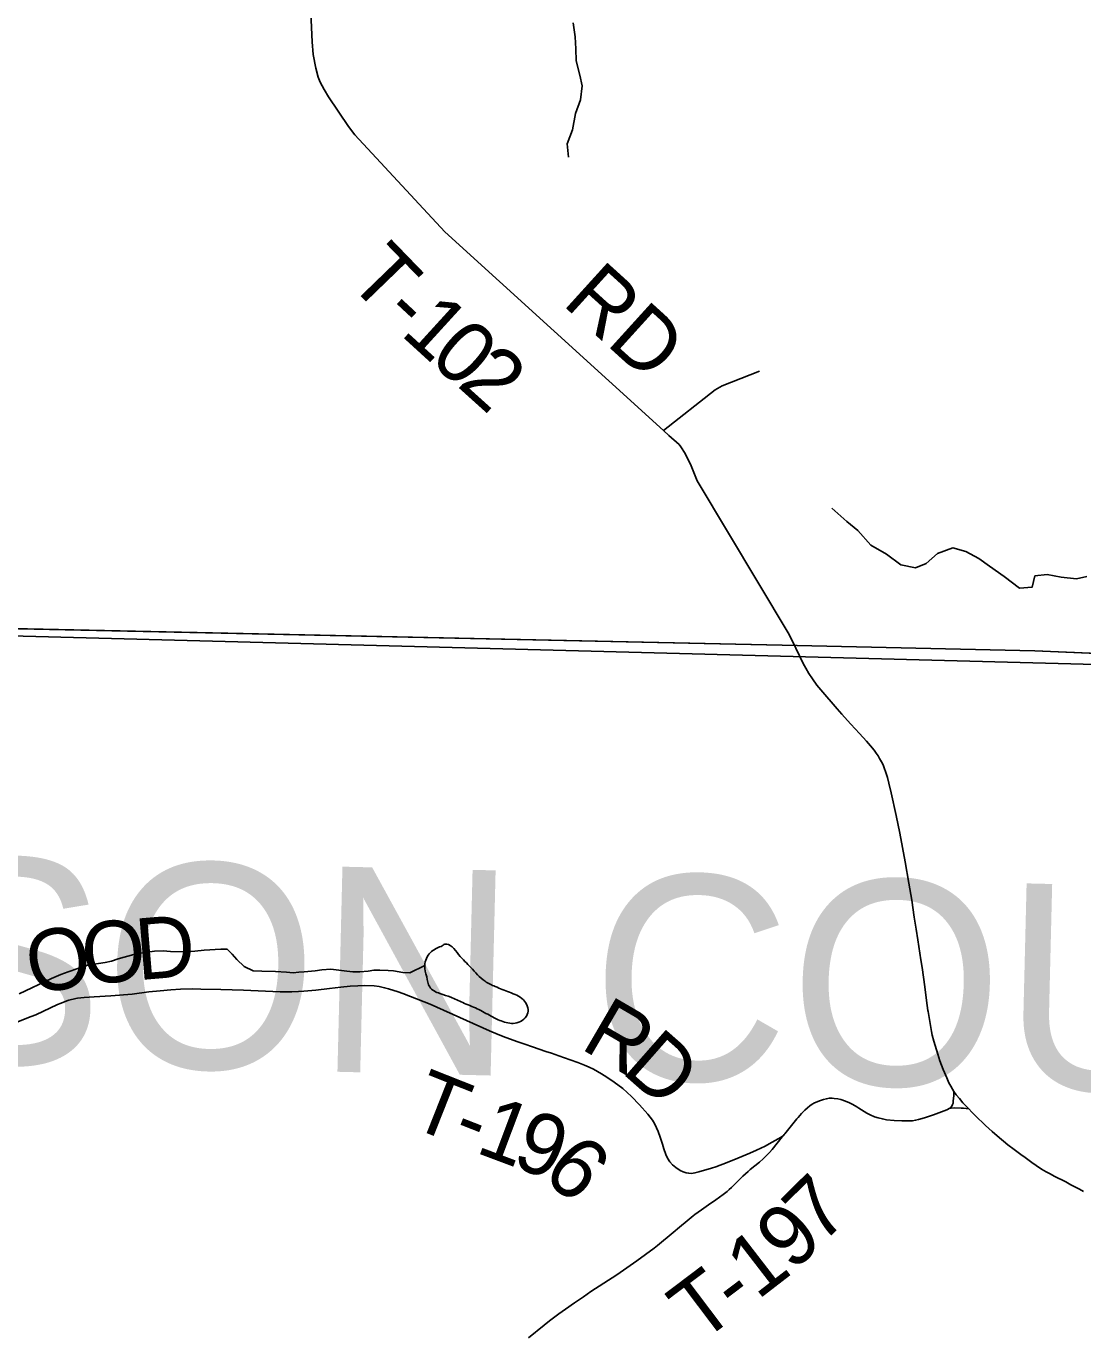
# Model space of a CAD drawing. Extents: x -1.2 to 34, y -8.5 to 22.
# Drawn here: x 3.478 to 4.454, y 17.02 to 18.225 of the extents above; entities that cross this region are included whole.
import ezdxf

# ---------------------------------------------------------------- set-up
doc = ezdxf.new("R2010")
doc.units = 0
for name, color, linetype in [('DV_X_County_Line', 7, 'Continuous'), ('GM_X_County_Road', 7, 'Continuous'), ('GM_X_County_Text', 7, 'Continuous'), ('GM_X_Minor_River', 7, 'Continuous'), ('GM_X_Township_Road', 7, 'Continuous'), ('GM_X_Township_Road_Text', 7, 'Continuous'), ('GM_X_Unincorporated_Text', 7, 'Continuous'), ('SH_Cut_Line', 7, 'Continuous')]:
    doc.layers.add(name, color=color, linetype=linetype)

msp = doc.modelspace()

# ---------------------------------------------------------------- linework, layer by layer
at = {"layer": 'DV_X_County_Line'}
msp.add_lwpolyline([(2.4258, 17.6899), (5.4446, 17.6102), (5.4511, 17.7337), (6.5684, 17.7149)], dxfattribs=at)
at = {"layer": 'GM_X_County_Road'}
msp.add_lwpolyline([(4.1824, 17.6639), (4.1886, 17.6513), (4.1955, 17.6371), (4.1977, 17.6329), (4.2007, 17.628), (4.2041, 17.6228), (4.2081, 17.6172), (4.2117, 17.6127), (4.2267, 17.5951), (4.231, 17.5902), (4.2362, 17.5846), (4.2395, 17.581), (4.2475, 17.5725), (4.254, 17.5654), (4.2576, 17.5611), (4.2608, 17.5571), (4.2629, 17.5544), (4.2646, 17.5518), (4.266, 17.5494), (4.2678, 17.5463), (4.2691, 17.5435), (4.2702, 17.5408), (4.2716, 17.5365), (4.2731, 17.5318), (4.2745, 17.5266), (4.2766, 17.5177), (4.2811, 17.4968), (4.2846, 17.4804), (4.2896, 17.4541), (4.293, 17.4344), (4.2957, 17.4186), (4.298, 17.403), (4.2998, 17.392), (4.3012, 17.3821), (4.3022, 17.376), (4.3041, 17.3637), (4.3052, 17.3565), (4.3065, 17.3476), (4.3077, 17.3385), (4.3094, 17.3261), (4.3106, 17.3168), (4.3107, 17.3158), (4.3139, 17.2974), (4.3145, 17.294), (4.3159, 17.2886), (4.3196, 17.2764), (4.3217, 17.2703), (4.3247, 17.2624), (4.3279, 17.2547), (4.33, 17.25), (4.3316, 17.2469), (4.3333, 17.2442), (4.3346, 17.2421), (4.3368, 17.2389), (4.3396, 17.2354), (4.3429, 17.2315), (4.3482, 17.226), (4.3512, 17.2229), (4.3541, 17.22), (4.3637, 17.2107), (4.3699, 17.205), (4.3745, 17.2011), (4.3845, 17.1929), (4.3903, 17.1884), (4.3963, 17.1839), (4.4003, 17.181), (4.4065, 17.1764), (4.4104, 17.1736), (4.4153, 17.1704), (4.4197, 17.1678), (4.4233, 17.1659), (4.4271, 17.1639), (4.4378, 17.1585), (4.4425, 17.156), (4.4469, 17.1537), (4.4505, 17.1517), (4.4541, 17.1496)], dxfattribs=at)
at = {"layer": 'GM_X_Minor_River'}
for points in [[(3.9831, 18.2284), (3.9847, 18.2155), (3.9856, 18.2045), (3.9857, 18.1935), (3.9892, 18.1803), (3.9912, 18.1704), (3.9898, 18.1575), (3.9853, 18.1449), (3.9824, 18.1297)], [(3.9824, 18.1297), (3.9776, 18.1167), (3.9788, 18.1046)], [(4.4572, 17.7173), (4.4477, 17.7153), (4.4337, 17.7167), (4.4207, 17.7192), (4.4093, 17.718), (4.4068, 17.7074), (4.395, 17.7065), (4.3809, 17.7174), (4.3675, 17.7268), (4.3576, 17.7339), (4.3457, 17.7406), (4.3335, 17.7439), (4.3195, 17.7385), (4.309, 17.7293), (4.2991, 17.7254), (4.2854, 17.7283), (4.2724, 17.7381), (4.2579, 17.7463), (4.246, 17.7599), (4.2357, 17.7681), (4.2219, 17.7805)], [(3.4713, 17.3321), (3.5014, 17.3463), (3.51, 17.3499), (3.5168, 17.3526), (3.5345, 17.3586), (3.5508, 17.3611), (3.5568, 17.3624), (3.5628, 17.3644), (3.5772, 17.3684), (3.5836, 17.3696), (3.5964, 17.3714), (3.6044, 17.3719), (3.6112, 17.3712), (3.6237, 17.371), (3.6335, 17.3716), (3.6422, 17.3724), (3.6577, 17.3734)], [(3.6577, 17.3734), (3.6634, 17.3735), (3.668, 17.3687), (3.6723, 17.3638), (3.6792, 17.3574), (3.6876, 17.3533), (3.6955, 17.3531), (3.708, 17.3529), (3.7183, 17.3523), (3.7243, 17.3516), (3.7296, 17.3521), (3.7345, 17.3525), (3.7447, 17.3535), (3.7508, 17.3543), (3.7591, 17.3548), (3.7739, 17.3531), (3.7796, 17.3525), (3.786, 17.3526), (3.7936, 17.3531), (3.7989, 17.3539), (3.8046, 17.354), (3.8121, 17.3537), (3.8171, 17.3534), (3.8258, 17.352), (3.8322, 17.3517), (3.8459, 17.3583)]]:
    msp.add_lwpolyline(points, dxfattribs=at)
for points in [[(3.861, 17.376), (3.8512, 17.3704), (3.8459, 17.3583), (3.8478, 17.348)], [(3.8478, 17.348), (3.8505, 17.3385), (3.86, 17.3324), (3.8699, 17.329), (3.881, 17.3241), (3.8943, 17.3184), (3.9073, 17.3115), (3.918, 17.3066), (3.931, 17.3054), (3.9412, 17.3146), (3.937, 17.3267), (3.9241, 17.3336), (3.9111, 17.3389), (3.9016, 17.3438), (3.8886, 17.3564), (3.8772, 17.3685), (3.8646, 17.378), (3.861, 17.376)]]:
    msp.add_spline(points, degree=3, dxfattribs=at)
at = {"layer": 'GM_X_Township_Road'}
for points in [[(4.1824, 17.6639), (4.0975, 17.8056), (4.0919, 17.8196), (4.0864, 17.8309), (4.0824, 17.8372), (4.0809, 17.8391), (4.0712, 17.8477), (4.0663, 17.8522), (3.8645, 18.0357), (3.7814, 18.1252), (3.7754, 18.1328), (3.7572, 18.1601), (3.753, 18.1668), (3.7493, 18.1737), (3.7476, 18.1782), (3.7453, 18.1865), (3.7428, 18.1991), (3.7419, 18.2108), (3.7375, 18.3122)], [(4.0663, 17.8522), (4.1142, 17.8896), (4.1207, 17.8933), (4.1552, 17.907)], [(3.4678, 17.3054), (3.4826, 17.3111), (3.4867, 17.3128), (3.5069, 17.3222), (3.5102, 17.3237), (3.5154, 17.3257), (3.5173, 17.3263), (3.5238, 17.328), (3.5253, 17.3282), (3.5316, 17.3287), (3.5407, 17.3293), (3.556, 17.3302), (3.5758, 17.332), (3.5913, 17.3339), (3.6015, 17.335), (3.6116, 17.336), (3.6204, 17.3365), (3.6314, 17.3368), (3.6391, 17.3366), (3.6576, 17.3363), (3.6787, 17.3357), (3.7123, 17.334), (3.717, 17.3339), (3.7232, 17.3339), (3.7295, 17.3342), (3.7343, 17.3346), (3.7454, 17.3357), (3.7579, 17.3371), (3.7684, 17.3382), (3.7771, 17.3391), (3.7841, 17.3397), (3.7901, 17.3399), (3.7991, 17.3395), (3.8038, 17.3389), (3.8088, 17.3378), (3.8126, 17.3368), (3.8215, 17.3339), (3.8257, 17.3324), (3.8455, 17.3248), (3.8508, 17.3226), (3.8844, 17.3076), (3.9058, 17.298), (3.9137, 17.2946), (3.9208, 17.2919), (3.932, 17.2879), (3.9383, 17.2857), (3.9454, 17.2832), (3.9515, 17.2811), (3.9578, 17.279), (3.9629, 17.2773), (3.9697, 17.2749), (3.975, 17.2731), (3.9803, 17.2712), (3.9873, 17.2687), (3.9936, 17.2663), (3.9978, 17.2646), (4.0017, 17.2627), (4.0055, 17.2606), (4.0091, 17.2583), (4.014, 17.2553), (4.0209, 17.2505), (4.0288, 17.2447), (4.0368, 17.2375), (4.0443, 17.2296), (4.0519, 17.2212), (4.0562, 17.2155), (4.058, 17.2124), (4.0599, 17.2084), (4.0614, 17.205), (4.0634, 17.1999), (4.0654, 17.1934), (4.0666, 17.1891), (4.0686, 17.1838), (4.0702, 17.1806), (4.0724, 17.1771), (4.0748, 17.1743), (4.0778, 17.1717), (4.0819, 17.169), (4.0845, 17.1678), (4.0873, 17.1669), (4.0897, 17.1665), (4.0923, 17.1664), (4.0954, 17.1668), (4.0991, 17.1677), (4.1108, 17.1712), (4.1148, 17.1726), (4.1253, 17.1765), (4.1351, 17.1805), (4.1461, 17.1851), (4.1524, 17.1878), (4.1603, 17.1916), (4.1641, 17.1936), (4.1724, 17.1982), (4.1751, 17.2), (4.1772, 17.2015), (4.1779, 17.2022), (4.1784, 17.2028), (4.1895, 17.2167), (4.1907, 17.2181), (4.1939, 17.2218), (4.197, 17.2248), (4.1993, 17.227), (4.2016, 17.2289), (4.2038, 17.2303), (4.2058, 17.2315), (4.2113, 17.2338), (4.2142, 17.2347), (4.2168, 17.2353), (4.2195, 17.2357), (4.222, 17.2357), (4.2241, 17.2356), (4.2274, 17.2352), (4.2301, 17.2346), (4.2344, 17.2332), (4.2382, 17.2315), (4.2413, 17.2299), (4.2448, 17.2279), (4.2468, 17.2266), (4.2541, 17.2221), (4.2571, 17.2205), (4.2612, 17.2187), (4.2645, 17.2176), (4.2685, 17.2167), (4.2722, 17.216), (4.2795, 17.2152), (4.2864, 17.2148), (4.2963, 17.215), (4.2991, 17.2154), (4.302, 17.2161), (4.3073, 17.2177), (4.3157, 17.2206), (4.3231, 17.2233), (4.328, 17.2252), (4.3307, 17.2265), (4.3314, 17.227), (4.3327, 17.2284), (4.3333, 17.2299), (4.3338, 17.2312), (4.334, 17.2333), (4.3344, 17.2381), (4.3346, 17.2421)], [(4.3307, 17.2265), (4.3321, 17.2266), (4.3351, 17.2269), (4.3412, 17.2267), (4.3434, 17.2266), (4.3459, 17.2263), (4.3482, 17.226)], [(3.9417, 17.0147), (3.9562, 17.0263), (3.9612, 17.0302), (3.9661, 17.0339), (3.9698, 17.0369), (3.9759, 17.0412), (3.9841, 17.0468), (3.9924, 17.0525), (3.9994, 17.0574), (4.0234, 17.0729), (4.0417, 17.0857), (4.0578, 17.0974), (4.061, 17.0999), (4.0754, 17.1117), (4.0813, 17.1167), (4.0883, 17.1226), (4.0939, 17.1273), (4.0954, 17.1285), (4.1014, 17.1329), (4.108, 17.1375), (4.1146, 17.1421), (4.1214, 17.1468), (4.1228, 17.148), (4.1251, 17.1498), (4.1271, 17.1516), (4.1291, 17.1534), (4.1347, 17.1588), (4.1398, 17.1638), (4.1446, 17.1683), (4.1465, 17.17), (4.1549, 17.1769), (4.1584, 17.18), (4.1617, 17.1832), (4.1643, 17.1858), (4.1666, 17.1885), (4.1761, 17.2001), (4.1772, 17.2015)]]:
    msp.add_lwpolyline(points, dxfattribs=at)
at = {"layer": 'GM_X_Unincorporated_Text'}
for p, q in [((4.1759, 17.654), (3.3984, 17.6707)), ((4.4093, 17.6489), (4.1759, 17.654)), ((4.6867, 17.6371), (4.4093, 17.6489))]:
    msp.add_line(p, q, dxfattribs=at)
msp.add_lwpolyline([(8.4143, 20.9), (2.465, 20.9), (2.4644, 20.6742), (2.4628, 20.1657), (2.4414, 19.0677), (2.4258, 17.6899), (2.8968, 17.6806), (3.3984, 17.6707), (4.1759, 17.654), (4.4093, 17.6489), (4.6867, 17.6371)], dxfattribs=at)
at = {"layer": 'SH_Cut_Line'}
for points in [[(8.9, 20.9), (2.465, 20.9), (2.4644, 20.6742), (2.4628, 20.1657), (2.4414, 19.0677), (2.4258, 17.6899), (2.8968, 17.6806), (3.3984, 17.6707), (4.1759, 17.654), (4.4093, 17.6489), (4.6867, 17.6371)], [(4.6867, 17.6371), (4.4093, 17.6489), (4.1759, 17.654), (3.3984, 17.6707), (2.8968, 17.6806), (2.4258, 17.6899), (2.4189, 17.3824), (2.402, 16.1209), (2.3867, 15.3183), (2.3672, 14.6322), (2.3643, 14.4203), (2.3586, 14.1), (8.9, 14.1)]]:
    msp.add_lwpolyline(points, dxfattribs=at)

# ---------------------------------------------------------------- texts
at = {"layer": 'GM_X_County_Text'}
msp.add_text('HARRISON COUNTY', height=0.189394, rotation=358.6005, dxfattribs=at).set_placement((2.591, 17.2889))
at = {"layer": 'GM_X_Township_Road_Text'}
for s, height, rotation, p in [('T', 0.0568, 314.0469, (3.7731, 17.9904)), ('RD', 0.05682, 317.7918, (3.9718, 17.9691)), ('-', 0.0568, 317.0684, (3.805, 17.9575)), ('1', 0.0568, 317.6344, (3.8225, 17.9412)), ('0', 0.0568, 317.9517, (3.8486, 17.9174)), ('2', 0.0568, 318.0315, (3.8747, 17.8939)), ('O', 0.0568, 11.5493, (3.4841, 17.3306)), ('O', 0.0568, 4.9749, (3.5314, 17.3404)), ('D', 0.0568, 4.7264, (3.5811, 17.3447)), ('R', 0.0568, 329.7207, (3.9884, 17.2823)), ('D', 0.0568, 318.6756, (4.0264, 17.2604)), ('T', 0.0568, 338.4071, (3.8294, 17.2108)), ('1', 0.0568, 339.3824, (3.8916, 17.1862)), ('-', 0.0568, 338.5705, (3.869, 17.1951)), ('9', 0.0568, 339.7078, (3.9247, 17.1738)), ('6', 0.0568, 318.3652, (3.9527, 17.1645)), ('7', 0.0568, 44.6587, (4.2117, 17.0995)), ('9', 0.0568, 43.8963, (4.1859, 17.0747)), ('1', 0.0568, 37.676, (4.1531, 17.0489)), ('T', 0.0568, 37.0593, (4.1001, 17.0088)), ('-', 0.0568, 37.173, (4.1341, 17.0345))]:
    msp.add_text(s, height=height, rotation=rotation, dxfattribs=at).set_placement(p)

doc.saveas('drawing.dxf')
